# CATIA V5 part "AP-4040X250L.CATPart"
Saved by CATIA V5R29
Part number: AP-4040X250L
Bounding box of the stored display mesh (mm): x -20 to 20, y -20 to 20, z 0 to 250
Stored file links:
  C:\Users\CDL\Desktop\PostConveyor\PostConveyor_Pipe\AP-4040X250L.CATPart
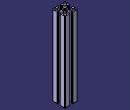
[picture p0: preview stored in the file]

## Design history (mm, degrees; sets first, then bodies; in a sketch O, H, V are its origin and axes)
Body1 (main body)
  Sketch1 on xy-plane, origin (0, 0, 0), H (1, 0, 0), V (0, 1, 0)
    circle A1 centre (13.5, -13.5) radius 4
    circle A2 centre (-13.5, -13.5) radius 4
    circle A3 centre (13.5, 13.5) radius 4
    circle A4 centre (-13.5, 13.5) radius 4
    line L1 (-4.45, 20) -> (-19, 20)
    arc A5 centre (-19, 19) radius 1 from (-19, 20) to (-20, 19) ccw
    line L2 (-20, 19) -> (-20, 4.45)
    arc A6 centre (-19.7, 4.45) radius 0.3 from (-20, 4.45) to (-19.7, 4.15) ccw
    line L3 (-19.7, 4.15) -> (-16.3, 4.15)
    arc A7 centre (-16.3, 4.45) radius 0.3 from (-16.3, 4.15) to (-16, 4.45) ccw
    line L4 (-16, 4.45) -> (-16, 6.85)
    arc A8 centre (-15.7, 6.85) radius 0.3 from (-15.7, 7.15) to (-16, 6.85) ccw
    line L5 (-15.7, 7.15) -> (-9.3585, 7.15)
    arc A9 centre (-9.3585, 6.85) radius 0.3 from (-9.1583, 7.0734) to (-9.3585, 7.15) ccw
    arc A10 centre (-15.5, 0) radius 9.5 from (-6.0049, 0.3049) to (-9.1583, 7.0734) ccw
    line L6 (-6.0049, 0.3049) -> (-5.7, 0)
    line L7 (-5.7, 0) -> (-6.0049, -0.3049)
    arc A11 centre (-15.5, 0) radius 9.5 from (-9.1583, -7.0734) to (-6.0049, -0.3049) ccw
    arc A12 centre (-9.3585, -6.85) radius 0.3 from (-9.3585, -7.15) to (-9.1583, -7.0734) ccw
    line L8 (-9.3585, -7.15) -> (-15.7, -7.15)
    arc A13 centre (-15.7, -6.85) radius 0.3 from (-16, -6.85) to (-15.7, -7.15) ccw
    line L9 (-16, -6.85) -> (-16, -4.45)
    arc A14 centre (-16.3, -4.45) radius 0.3 from (-16, -4.45) to (-16.3, -4.15) ccw
    line L10 (-16.3, -4.15) -> (-19.7, -4.15)
    arc A15 centre (-19.7, -4.45) radius 0.3 from (-19.7, -4.15) to (-20, -4.45) ccw
    line L11 (-20, -4.45) -> (-20, -19)
    arc A16 centre (-19, -19) radius 1 from (-20, -19) to (-19, -20) ccw
    line L12 (-19, -20) -> (-4.45, -20)
    arc A17 centre (-4.45, -19.7) radius 0.3 from (-4.45, -20) to (-4.15, -19.7) ccw
    line L13 (-4.15, -19.7) -> (-4.15, -16.3)
    arc A18 centre (-4.45, -16.3) radius 0.3 from (-4.15, -16.3) to (-4.45, -16) ccw
    line L14 (-4.45, -16) -> (-6.85, -16)
    arc A19 centre (-6.85, -15.7) radius 0.3 from (-7.15, -15.7) to (-6.85, -16) ccw
    line L15 (-7.15, -15.7) -> (-7.15, -9.3585)
    arc A20 centre (-6.85, -9.3585) radius 0.3 from (-7.0734, -9.1583) to (-7.15, -9.3585) ccw
    arc A21 centre (0, -15.5) radius 9.5 from (-0.3049, -6.0049) to (-7.0734, -9.1583) ccw
    line L16 (-0.3049, -6.0049) -> (0, -5.7)
    line L17 (0, -5.7) -> (0.3049, -6.0049)
    arc A22 centre (0, -15.5) radius 9.5 from (7.0734, -9.1583) to (0.3049, -6.0049) ccw
    arc A23 centre (6.85, -9.3585) radius 0.3 from (7.15, -9.3585) to (7.0734, -9.1583) ccw
    line L18 (7.15, -9.3585) -> (7.15, -15.7)
    arc A24 centre (6.85, -15.7) radius 0.3 from (6.85, -16) to (7.15, -15.7) ccw
    line L19 (6.85, -16) -> (4.45, -16)
    arc A25 centre (4.45, -16.3) radius 0.3 from (4.45, -16) to (4.15, -16.3) ccw
    line L20 (4.15, -16.3) -> (4.15, -19.7)
    arc A26 centre (4.45, -19.7) radius 0.3 from (4.15, -19.7) to (4.45, -20) ccw
    line L21 (4.45, -20) -> (19, -20)
    arc A27 centre (19, -19) radius 1 from (19, -20) to (20, -19) ccw
    line L22 (20, -19) -> (20, -4.45)
    arc A28 centre (19.7, -4.45) radius 0.3 from (20, -4.45) to (19.7, -4.15) ccw
    line L23 (19.7, -4.15) -> (16.3, -4.15)
    arc A29 centre (16.3, -4.45) radius 0.3 from (16.3, -4.15) to (16, -4.45) ccw
    line L24 (16, -4.45) -> (16, -6.85)
    arc A30 centre (15.7, -6.85) radius 0.3 from (15.7, -7.15) to (16, -6.85) ccw
    line L25 (15.7, -7.15) -> (9.3585, -7.15)
    arc A31 centre (9.3585, -6.85) radius 0.3 from (9.1583, -7.0734) to (9.3585, -7.15) ccw
    arc A32 centre (15.5, 0) radius 9.5 from (6.0049, -0.3049) to (9.1583, -7.0734) ccw
    line L26 (6.0049, -0.3049) -> (5.7, 0)
    line L27 (5.7, 0) -> (6.0049, 0.3049)
    arc A33 centre (15.5, 0) radius 9.5 from (9.1583, 7.0734) to (6.0049, 0.3049) ccw
    arc A34 centre (9.3585, 6.85) radius 0.3 from (9.3585, 7.15) to (9.1583, 7.0734) ccw
    line L28 (9.3585, 7.15) -> (15.7, 7.15)
    arc A35 centre (15.7, 6.85) radius 0.3 from (16, 6.85) to (15.7, 7.15) ccw
    line L29 (16, 6.85) -> (16, 4.45)
    arc A36 centre (16.3, 4.45) radius 0.3 from (16, 4.45) to (16.3, 4.15) ccw
    line L30 (16.3, 4.15) -> (19.7, 4.15)
    arc A37 centre (19.7, 4.45) radius 0.3 from (19.7, 4.15) to (20, 4.45) ccw
    line L31 (20, 4.45) -> (20, 19)
    arc A38 centre (19, 19) radius 1 from (20, 19) to (19, 20) ccw
    line L32 (19, 20) -> (4.45, 20)
    arc A39 centre (4.45, 19.7) radius 0.3 from (4.45, 20) to (4.15, 19.7) ccw
    line L33 (4.15, 19.7) -> (4.15, 16.3)
    arc A40 centre (4.45, 16.3) radius 0.3 from (4.15, 16.3) to (4.45, 16) ccw
    line L34 (4.45, 16) -> (6.85, 16)
    arc A41 centre (6.85, 15.7) radius 0.3 from (7.15, 15.7) to (6.85, 16) ccw
    line L35 (7.15, 15.7) -> (7.15, 9.3585)
    arc A42 centre (6.85, 9.3585) radius 0.3 from (7.0734, 9.1583) to (7.15, 9.3585) ccw
    arc A43 centre (0, 15.5) radius 9.5 from (0.3049, 6.0049) to (7.0734, 9.1583) ccw
    line L36 (0.3049, 6.0049) -> (0, 5.7)
    line L37 (0, 5.7) -> (-0.3049, 6.0049)
    arc A44 centre (0, 15.5) radius 9.5 from (-7.0734, 9.1583) to (-0.3049, 6.0049) ccw
    arc A45 centre (-6.85, 9.3585) radius 0.3 from (-7.15, 9.3585) to (-7.0734, 9.1583) ccw
    line L38 (-7.15, 9.3585) -> (-7.15, 15.7)
    arc A46 centre (-6.85, 15.7) radius 0.3 from (-6.85, 16) to (-7.15, 15.7) ccw
    line L39 (-6.85, 16) -> (-4.45, 16)
    arc A47 centre (-4.45, 16.3) radius 0.3 from (-4.45, 16) to (-4.15, 16.3) ccw
    line L40 (-4.15, 16.3) -> (-4.15, 19.7)
    arc A48 centre (-4.45, 19.7) radius 0.3 from (-4.15, 19.7) to (-4.45, 20) ccw
    arc A49 centre (-2.9189, -3.5553) radius 0.3 from (-3.1093, -3.7872) to (-2.7068, -3.7674) ccw
    line L41 (-2.7068, -3.7674) -> (-1.8146, -2.8753)
    arc A50 centre (0, 0) radius 3.4 from (-1.8146, -2.8753) to (1.8146, -2.8753) ccw
    line L42 (1.8146, -2.8753) -> (2.7068, -3.7674)
    arc A51 centre (2.9189, -3.5553) radius 0.3 from (2.7068, -3.7674) to (3.1093, -3.7872) ccw
    arc A52 centre (0, 0) radius 4.9 from (3.1093, -3.7872) to (3.7872, -3.1093) ccw
    arc A53 centre (3.5553, -2.9189) radius 0.3 from (3.7872, -3.1093) to (3.7674, -2.7068) ccw
    line L43 (3.7674, -2.7068) -> (2.8753, -1.8146)
    arc A54 centre (0, 0) radius 3.4 from (2.8753, -1.8146) to (2.8753, 1.8146) ccw
    line L44 (2.8753, 1.8146) -> (3.7674, 2.7068)
    arc A55 centre (3.5553, 2.9189) radius 0.3 from (3.7674, 2.7068) to (3.7872, 3.1093) ccw
    arc A56 centre (0, 0) radius 4.9 from (3.7872, 3.1093) to (3.1093, 3.7872) ccw
    arc A57 centre (2.9189, 3.5553) radius 0.3 from (3.1093, 3.7872) to (2.7068, 3.7674) ccw
    line L45 (2.7068, 3.7674) -> (1.8146, 2.8753)
    arc A58 centre (0, 0) radius 3.4 from (1.8146, 2.8753) to (-1.8146, 2.8753) ccw
    line L46 (-1.8146, 2.8753) -> (-2.7068, 3.7674)
    arc A59 centre (-2.9189, 3.5553) radius 0.3 from (-2.7068, 3.7674) to (-3.1093, 3.7872) ccw
    arc A60 centre (0, 0) radius 4.9 from (-3.1093, 3.7872) to (-3.7872, 3.1093) ccw
    arc A61 centre (-3.5553, 2.9189) radius 0.3 from (-3.7872, 3.1093) to (-3.7674, 2.7068) ccw
    line L47 (-3.7674, 2.7068) -> (-2.8753, 1.8146)
    arc A62 centre (0, 0) radius 3.4 from (-2.8753, 1.8146) to (-2.8753, -1.8146) ccw
    line L48 (-2.8753, -1.8146) -> (-3.7674, -2.7068)
    arc A63 centre (-3.5553, -2.9189) radius 0.3 from (-3.7674, -2.7068) to (-3.7872, -3.1093) ccw
    arc A64 centre (0, 0) radius 4.9 from (-3.7872, -3.1093) to (-3.1093, -3.7872) ccw
    point P1 (-4.45, 20)
    point P2 (-19, 20)
    point P3 (-19, 20)
    point P4 (-20, 19)
    point P5 (-20, 19)
    point P6 (-20, 4.45)
    point P7 (-20, 4.45)
    point P8 (-19.7, 4.15)
    point P9 (-19.7, 4.15)
    point P10 (-16.3, 4.15)
    point P11 (-16.3, 4.15)
    point P12 (-16, 4.45)
    point P13 (-16, 4.45)
    point P14 (-16, 6.85)
    point P15 (-15.7, 7.15)
    point P16 (-16, 6.85)
    point P17 (-15.7, 7.15)
    point P18 (-9.3585, 7.15)
    point P19 (-9.1583, 7.0734)
    point P20 (-9.3585, 7.15)
    point P21 (-6.0049, 0.3049)
    point P22 (-9.1583, 7.0734)
    point P23 (-6.0049, 0.3049)
    point P24 (-5.7, 0)
    point P25 (-5.7, 0)
    point P26 (-6.0049, -0.3049)
    point P27 (-9.1583, -7.0734)
    point P28 (-6.0049, -0.3049)
    point P29 (-9.3585, -7.15)
    point P30 (-9.1583, -7.0734)
    point P31 (-9.3585, -7.15)
    point P32 (-15.7, -7.15)
    point P33 (-16, -6.85)
    point P34 (-15.7, -7.15)
    point P35 (-16, -6.85)
    point P36 (-16, -4.45)
    point P37 (-16, -4.45)
    point P38 (-16.3, -4.15)
    point P39 (-16.3, -4.15)
    point P40 (-19.7, -4.15)
    point P41 (-19.7, -4.15)
    point P42 (-20, -4.45)
    point P43 (-20, -4.45)
    point P44 (-20, -19)
    point P45 (-20, -19)
    point P46 (-19, -20)
    point P47 (-19, -20)
    point P48 (-4.45, -20)
    point P49 (-4.45, -20)
    point P50 (-4.15, -19.7)
    point P51 (-4.15, -19.7)
    point P52 (-4.15, -16.3)
    point P53 (-4.15, -16.3)
    point P54 (-4.45, -16)
    point P55 (-4.45, -16)
    point P56 (-6.85, -16)
    point P57 (-7.15, -15.7)
    point P58 (-6.85, -16)
    point P59 (-7.15, -15.7)
    point P60 (-7.15, -9.3585)
    point P61 (-7.0734, -9.1583)
    point P62 (-7.15, -9.3585)
    point P63 (-0.3049, -6.0049)
    point P64 (-7.0734, -9.1583)
    point P65 (-0.3049, -6.0049)
    point P66 (0, -5.7)
    point P67 (0, -5.7)
    point P68 (0.3049, -6.0049)
    point P69 (7.0734, -9.1583)
    point P70 (0.3049, -6.0049)
    point P71 (7.15, -9.3585)
    point P72 (7.0734, -9.1583)
    point P73 (7.15, -9.3585)
    point P74 (7.15, -15.7)
    point P75 (6.85, -16)
    point P76 (7.15, -15.7)
    point P77 (6.85, -16)
    point P78 (4.45, -16)
    point P79 (4.45, -16)
    point P80 (4.15, -16.3)
    point P81 (4.15, -16.3)
    point P82 (4.15, -19.7)
    point P83 (4.15, -19.7)
    point P84 (4.45, -20)
    point P85 (4.45, -20)
    point P86 (19, -20)
    point P87 (19, -20)
    point P88 (20, -19)
    point P89 (20, -19)
    point P90 (20, -4.45)
    point P91 (20, -4.45)
    point P92 (19.7, -4.15)
    point P93 (19.7, -4.15)
    point P94 (16.3, -4.15)
    point P95 (16.3, -4.15)
    point P96 (16, -4.45)
    point P97 (16, -4.45)
    point P98 (16, -6.85)
    point P99 (15.7, -7.15)
    point P100 (16, -6.85)
    point P101 (15.7, -7.15)
    point P102 (9.3585, -7.15)
    point P103 (9.1583, -7.0734)
    point P104 (9.3585, -7.15)
    point P105 (6.0049, -0.3049)
    point P106 (9.1583, -7.0734)
    point P107 (6.0049, -0.3049)
    point P108 (5.7, 0)
    point P109 (5.7, 0)
    point P110 (6.0049, 0.3049)
    point P111 (9.1583, 7.0734)
    point P112 (6.0049, 0.3049)
    point P113 (9.3585, 7.15)
    point P114 (9.1583, 7.0734)
    point P115 (9.3585, 7.15)
    point P116 (15.7, 7.15)
    point P117 (16, 6.85)
    point P118 (15.7, 7.15)
    point P119 (16, 6.85)
    point P120 (16, 4.45)
    point P121 (16, 4.45)
    point P122 (16.3, 4.15)
    point P123 (16.3, 4.15)
    point P124 (19.7, 4.15)
    point P125 (19.7, 4.15)
    point P126 (20, 4.45)
    point P127 (20, 4.45)
    point P128 (20, 19)
    point P129 (20, 19)
    point P130 (19, 20)
    point P131 (19, 20)
    point P132 (4.45, 20)
    point P133 (4.45, 20)
    point P134 (4.15, 19.7)
    point P135 (4.15, 19.7)
    point P136 (4.15, 16.3)
    point P137 (4.15, 16.3)
    point P138 (4.45, 16)
    point P139 (4.45, 16)
    point P140 (6.85, 16)
    point P141 (7.15, 15.7)
    point P142 (6.85, 16)
    point P143 (7.15, 15.7)
    point P144 (7.15, 9.3585)
    point P145 (7.0734, 9.1583)
    point P146 (7.15, 9.3585)
    point P147 (0.3049, 6.0049)
    point P148 (7.0734, 9.1583)
    point P149 (0.3049, 6.0049)
    point P150 (0, 5.7)
    point P151 (0, 5.7)
    point P152 (-0.3049, 6.0049)
    point P153 (-7.0734, 9.1583)
    point P154 (-0.3049, 6.0049)
    point P155 (-7.15, 9.3585)
    point P156 (-7.0734, 9.1583)
    point P157 (-7.15, 9.3585)
    point P158 (-7.15, 15.7)
    point P159 (-6.85, 16)
    point P160 (-7.15, 15.7)
    point P161 (-6.85, 16)
    point P162 (-4.45, 16)
    point P163 (-4.45, 16)
    point P164 (-4.15, 16.3)
    point P165 (-4.15, 16.3)
    point P166 (-4.15, 19.7)
    point P167 (-4.15, 19.7)
    point P168 (-4.45, 20)
    point P169 (-3.1093, -3.7872)
    point P170 (-2.7068, -3.7674)
    point P171 (-2.7068, -3.7674)
    point P172 (-1.8146, -2.8753)
    point P173 (-1.8146, -2.8753)
    point P174 (1.8146, -2.8753)
    point P175 (1.8146, -2.8753)
    point P176 (2.7068, -3.7674)
    point P177 (2.7068, -3.7674)
    point P178 (3.1093, -3.7872)
    point P179 (3.1093, -3.7872)
    point P180 (3.7872, -3.1093)
    point P181 (3.7872, -3.1093)
    point P182 (3.7674, -2.7068)
    point P183 (3.7674, -2.7068)
    point P184 (2.8753, -1.8146)
    point P185 (2.8753, -1.8146)
    point P186 (2.8753, 1.8146)
    point P187 (2.8753, 1.8146)
    point P188 (3.7674, 2.7068)
    point P189 (3.7674, 2.7068)
    point P190 (3.7872, 3.1093)
    point P191 (3.7872, 3.1093)
    point P192 (3.1093, 3.7872)
    point P193 (3.1093, 3.7872)
    point P194 (2.7068, 3.7674)
    point P195 (2.7068, 3.7674)
    point P196 (1.8146, 2.8753)
    point P197 (1.8146, 2.8753)
    point P198 (-1.8146, 2.8753)
    point P199 (-1.8146, 2.8753)
    point P200 (-2.7068, 3.7674)
    point P201 (-2.7068, 3.7674)
    point P202 (-3.1093, 3.7872)
    point P203 (-3.1093, 3.7872)
    point P204 (-3.7872, 3.1093)
    point P205 (-3.7872, 3.1093)
    point P206 (-3.7674, 2.7068)
    point P207 (-3.7674, 2.7068)
    point P208 (-2.8753, 1.8146)
    point P209 (-2.8753, 1.8146)
    point P210 (-2.8753, -1.8146)
    point P211 (-2.8753, -1.8146)
    point P212 (-3.7674, -2.7068)
    point P213 (-3.7674, -2.7068)
    point P214 (-3.7872, -3.1093)
    point P215 (-3.7872, -3.1093)
    point P216 (-3.1093, -3.7872)
    distance L31 V = 20
    distance L32 H = 20
    coincidence: P1 P168, P2 P3, P4 P5, P6 P7, P8 P9, P10 P11, P12 P13, P14 P16, P15 P17, P18 P20, P19 P22, P21 P23, P24 P25, P26 P28, P27 P30, P29 P31, P32 P34, P33 P35, P36 P37, P38 P39, P40 P41, P42 P43, P49 P48, P50 P51, P52 P53, P54 P55, P56 P58, P57 P59, P60 P62, P61 P64, P63 P65, P66 P67, P68 P70, P69 P72, P71 P73, P74 P76, P75 P77, P78 P79, P80 P81, P82 P83, P84 P85, P86 P87, P88 P89, P90 P91, P92 P93, P94 P95, P96 P97, P98 P100, P99 P101, P102 P104, P103 P106, P105 P107, P108 P109, P110 P112, P111 P114, P113 P115, P116 P118, P117 P119, P120 P121, P122 P123, P124 P125, P126 P127, P128 P129, P130 P131, P132 P133, P134 P135, P136 P137, P138 P139, P140 P142, P141 P143, P144 P146, P145 P148, P147 P149, P150 P151, P152 P154, P153 P156, P155 P157, P158 P160, P159 P161, P162 P163, P164 P165, P166 P167, P169 P216, P170 P171, P172 P173, P174 P175, P176 P177, P178 P179, P180 P181, P182 P183, P184 P185, P186 P187, P188 P189, P190 P191, P192 P193, P194 P195, P196 P197, P198 P199, P200 P201, P202 P203, P204 P205, P206 P207, P208 P209, P210 P211, P212 P213, P214 P215, P47 P46, P44 P45
  Pad1: profile Sketch1, direction (0, 0, 1), length 250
